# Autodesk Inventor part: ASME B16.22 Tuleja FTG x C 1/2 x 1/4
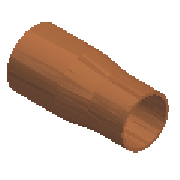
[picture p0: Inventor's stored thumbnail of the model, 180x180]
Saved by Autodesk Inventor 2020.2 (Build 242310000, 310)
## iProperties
Manager: www.cadconsulting.pl
Company: Fabian Stasiak CAD Consulting
IsCustomPart: 0
NAME: PIPING: ASME B16.22 Bushing FTG x C
DATA: <meta><inlinegroups number="1" deflen="2.54"></inlinegroups><connections number="2"></connections><angles><a>3.14159265358979</a></angles></meta>
Created: 2014-02
Part Number: ASME B16.22 Tuleja FTG x C 1/2 x 1/4
Material: Miedź kuta
Description: Tuleja
Document SubType Name: Modeling
Standard: ASME B16.22
Designer: F.Stasiak
Standard Revision: 2001
Standards Organization: ANSI
Language: pl-PL
Size Designation: 1/2 x 1/4
Categories: <MemberInstance><Categories><Category DisplayName="Rury cienko- i grubościenne" InternalName="4347fa0f-2144-441d-94cd-e3e15c92b736" Mnemonic="TUBEANDPIPE"><Cate
Density: 1 g/cm^3
Appearance: Miedź - satynowa
Catalog Web Link: www.expertbooks.pl
Author: F.Stasiak
Subject: Zbiór ćwiczeń. Autodesk Inventor 2020. Kurs Professional
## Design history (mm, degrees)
sketch "Sketch1"
  geometry: L1 (0, 0)-(-31.75, 0); L2 (0, 0)-(0, 7.163); L3 (0, 7.163)-(0, 7.899); L4 (0, 7.899)-(-14.224, 7.899); L5 (-14.224, 7.899)-(-23.876, 5.372); L6 (-23.876, 5.372)-(-31.75, 5.372); L7 (-31.75, 5.372)-(-31.75, 4.788); L8 (-31.75, 4.788)-(-23.916, 4.788); L9 (-14.224, 7.163)-(0, 7.163); L10 (-31.75, 4.788)-(-31.75, 0); L11 (-23.876, 5.372)-(-23.876, 0); L12 (-14.224, 7.899)-(-14.224, 7.163); L13 (-23.876, 4.635)-(-14.224, 7.163); L14 (-23.876, 4.635)-(-23.916, 4.788); L15 (-14.224, 7.163)-(-14.224, 0); 1 further point
  constraints: 30 end point, 6 perpendicular, 5 parallel, 3 point on line, 1 coincident, 1 collinear, 1 horizontal
  dimensions: "d0" = 0.5842 distance of L6.end L7.end (= T2); "d1" = 0.7366 distance of L2.end L3.end (= T1); "d2" = 7.8994 distance of L1.start L3.end (= 0.5 x A); "d3" = 4.7879 distance of L7.end L1.end (= 0.5 x F1); "d4" = 7.874 distance of L11.end L1.end (= G); "d5" = 14.224 horizontal distance of L9.start L1.start (= K1); "d6" = 23.876 distance of L1.start L11.end (= L); "d7" = 0.7366 distance of L13.start L5.end (= T1)
revolve "Revolve1" sketch "Sketch1" stored, may be unused: angle "d9" = 90 deg
workpoint "Work Point1"
workpoint "Work Point2"
workaxis "Work Axis1"
workpoint "Work Point3"
workaxis "Work Axis2"
workpoint "Work Point4"
body "Solid1"
other parameters: "L" = 23.876 [user parameter; used in 1 equation term], "G" = 7.874 [user parameter; used in 1 equation term], "T1" = 0.7366 [user parameter; used in 2 equation terms], "F1" = 9.5758 [user parameter; used in 1 equation term], "A" = 15.7988 [user parameter; used in 1 equation term], "T2" = 0.5842 [user parameter; used in 1 equation term], "K1" = 14.224 [user parameter; used in 1 equation term], "Size_Designation" = 12.345 [user parameter]
